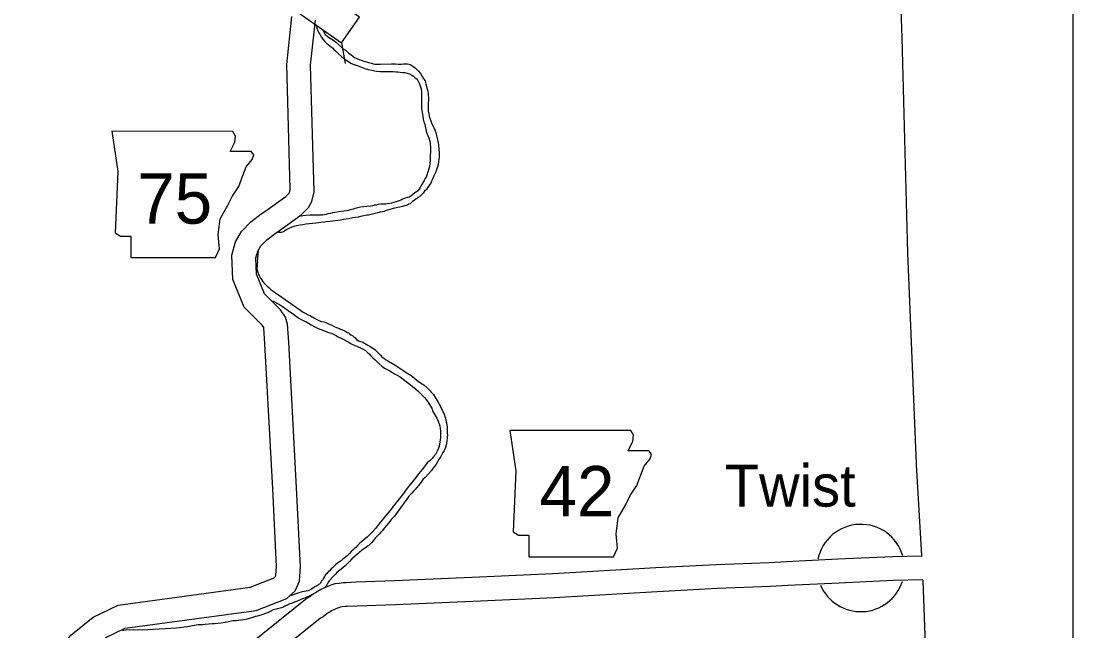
# Model space of a CAD drawing. Extents: x 1720274 to 1751788, y 372074 to 391887.
# Drawn here: x 1724650 to 1726742, y 388953 to 390167 of the extents above; entities that cross this region are included whole.
import ezdxf

# ---------------------------------------------------------------- set-up
doc = ezdxf.new("R2010")
doc.units = 0
for name, color, linetype in [('Level 10', 7, 'Continuous'), ('Level 2', 7, 'Continuous'), ('Level 20', 7, 'Continuous'), ('Level 21', 7, 'Continuous'), ('Level 24', 7, 'Continuous'), ('Level 9', 7, 'Continuous'), ('R_Draft', 7, 'Continuous')]:
    doc.layers.add(name, color=color, linetype=linetype)

msp = doc.modelspace()

# ---------------------------------------------------------------- linework, layer by layer
at = {"layer": 'Level 10'}
for points in [[(1724842.8, 389004.8), (1725105.5, 389040.3), (1725153, 389059), (1725155.6, 389061.3), (1725156.7, 389063.9), (1725158.1, 389081.6), (1725150.4, 389235.7), (1725134.8, 389524.6), (1725132.6, 389556), (1725132.4, 389556.9), (1725129, 389561.7), (1725093.8, 389597.5), (1725070.9, 389652.7), (1725069.1, 389701), (1725076.4, 389727.3), (1725088.4, 389747.9), (1725106.6, 389767.2), (1725127.6, 389783), (1725136.5, 389788.8), (1725176.1, 389817.5), (1725183.2, 389824.4), (1725183.4, 389824.9), (1725185.3, 389832.4), (1725178.1, 390080.5), (1725188.5, 390175.8)], [(1724856.7, 388958.8), (1725117.5, 388994.1), (1725178.5, 389018.1), (1725195.2, 389033.3), (1725203.3, 389052.4), (1725205.7, 389080.8), (1725197.7, 389238.1), (1725182.1, 389527.6), (1725179.6, 389563.9), (1725175.9, 389577.3), (1725165.5, 389592.1), (1725134, 389624.1), (1725118, 389663), (1725116.7, 389695.4), (1725120.4, 389708.7), (1725126.6, 389719.3), (1725138.4, 389731.7), (1725154.9, 389744.2), (1725163.5, 389749.8), (1725206.8, 389781.2), (1725221.6, 389795.7), (1725228, 389807.7), (1725232.9, 389827.1), (1725225.5, 390078.6), (1725235.3, 390168.4)], [(1726442.2, 389102.2), (1726382.7, 389100.8), (1726274.3, 389095.9), (1726172.4, 389090.9), (1726137.4, 389089), (1726032.3, 389085), (1725912.1, 389078.5), (1725707.6, 389066.7), (1725561.2, 389060.1), (1725392.5, 389052.7), (1725316.3, 389050), (1725296.5, 389049.1), (1725290.4, 389048.8), (1725282.7, 389047.9), (1725273.8, 389046.7), (1725267.6, 389044.8), (1725261.2, 389042.3), (1725246, 389035.6), (1725239.4, 389031.8), (1725236.5, 389029.8), (1725231.6, 389026.9), (1725224.4, 389021.4), (1725218.7, 389018.3)], [(1726443.2, 389054.8), (1726384.3, 389053.4), (1726276.5, 389048.5), (1726174.9, 389043.5), (1726139.6, 389041.6), (1726034.5, 389037.6), (1725914.7, 389031.2), (1725710.1, 389019.4), (1725563.3, 389012.7), (1725394.4, 389005.4), (1725318.2, 389002.6), (1725298.6, 389001.8), (1725294.2, 389001.6), (1725288.7, 389000.9), (1725284.1, 389000.3), (1725283.1, 389000), (1725279.3, 388998.5), (1725267.5, 388993.3), (1725264.5, 388991.6), (1725261.9, 388989.8), (1725258.2, 388987.6), (1725250.3, 388981.6), (1725245.1, 388978.7)], [(1725218.7, 389018.3), (1724974.9, 388822.1)], [(1724661.1, 388686.1), (1724664.3, 388796.5), (1724695.8, 388863.1), (1724724.8, 388912.7), (1724748.7, 388944.8), (1724793.2, 388980.5), (1724842.8, 389004.8)], [(1725245.1, 388978.7), (1725004.5, 388785.1)], [(1724708.8, 388694.5), (1724711.4, 388785.3), (1724737.8, 388841), (1724764.3, 388886.5), (1724783.1, 388911.6), (1724818.7, 388940.3), (1724856.7, 388958.8)]]:
    msp.add_lwpolyline(points, dxfattribs=at)
at = {"layer": 'Level 2'}
for points in [[(1726441.2, 389103.1), (1726430.6, 389283.7), (1726430.4, 389285.5), (1726413.3, 389705), (1726402, 390133.2), (1726387.2, 390548.1), (1726369.4, 390969.9), (1725968.9, 390955)], [(1726443.9, 389052.9), (1726443.8, 389053.9)], [(1726517.5, 386794.1), (1726507.7, 387180.9), (1726508, 387187.3), (1726491.7, 387614.2), (1726479.2, 388029.9), (1726479.1, 388035), (1726467.4, 388445.5), (1726450.4, 388867), (1726450.4, 388871.1), (1726443.9, 389052.9)]]:
    msp.add_lwpolyline(points, dxfattribs=at)
at = {"layer": 'Level 20'}
msp.add_line((1725287.1, 390123.3), (1725294.1, 390082.2), dxfattribs=at)
msp.add_lwpolyline([(1725133.7, 390231.6), (1725287.1, 390123.3), (1725323.1, 390174.4), (1725169.8, 390282.7)], close=True, dxfattribs=at)
at = {"layer": 'Level 21'}
for points in [[(1724830.4, 389947.3), (1724842.4, 389867.1), (1724837.1, 389745.4), (1724847.8, 389738.8), (1724867.8, 389738.8), (1724867.8, 389696), (1725036.2, 389696), (1725044.2, 389713.4), (1725041.6, 389741.4), (1725045.6, 389773.5), (1725060.3, 389798.9), (1725069.6, 389817.6), (1725083, 389837.7), (1725091, 389859.1), (1725097.7, 389876.4), (1725109.7, 389891.1), (1725112.4, 389900.5), (1725107.1, 389907.2), (1725065.6, 389907.2), (1725075, 389925.9), (1725076.3, 389937.9), (1725070.8, 389947.1)], [(1725621.8, 389352), (1725633.9, 389271.8), (1725628.5, 389150.2), (1725639.2, 389143.5), (1725659.3, 389143.5), (1725659.3, 389100.7), (1725827.7, 389100.7), (1725835.7, 389118.1), (1725833, 389146.2), (1725837, 389178.3), (1725851.7, 389203.7), (1725861.1, 389222.4), (1725874.4, 389242.4), (1725882.5, 389263.8), (1725889.1, 389281.2), (1725901.2, 389295.9), (1725903.8, 389305.2), (1725898.5, 389311.9), (1725857.1, 389311.9), (1725866.4, 389330.6), (1725867.8, 389342.6), (1725862.2, 389351.9)]]:
    msp.add_lwpolyline(points, close=True, dxfattribs=at)
at = {"layer": 'Level 24'}
for start, end in [(16.0112, 168.3106), (202.9489, 342.1811)]:
    msp.add_arc((1726319.8, 389078.5), 86.9, start, end, dxfattribs=at)
at = {"layer": 'Level 9'}
for points in [[(1725236.8, 390159), (1725237.1, 390155.9), (1725238, 390152.3), (1725239.8, 390147.3), (1725242.2, 390143.2), (1725244, 390140.3), (1725246, 390136.3), (1725250.1, 390130.6), (1725253.5, 390126.9), (1725257, 390123), (1725267.5, 390114.9), (1725269.4, 390113.1), (1725272, 390110.3), (1725276.3, 390106), (1725281, 390101.5), (1725287, 390096), (1725291, 390093.1), (1725295.8, 390089.4), (1725300.7, 390086.1)], [(1725250.1, 390150.1), (1725250.9, 390147.2), (1725252.8, 390143.2), (1725254.8, 390140.2), (1725257.3, 390137.8), (1725259.3, 390135.7), (1725262.3, 390133.7), (1725265.3, 390132.2), (1725267.3, 390131.2), (1725270.1, 390129.1), (1725272.3, 390127.5), (1725277.3, 390123.7), (1725281.8, 390119.1), (1725290.1, 390111.5), (1725295, 390108.7), (1725301.3, 390103.4), (1725306, 390099.5), (1725313, 390094.1), (1725322.3, 390090.5), (1725326.4, 390089.1), (1725333.7, 390086.3), (1725337.1, 390085.3), (1725340.8, 390084.4), (1725343.4, 390083.8), (1725346.5, 390082.8), (1725347.6, 390082.6), (1725350, 390081.8), (1725353.1, 390081.2), (1725357.2, 390080.6), (1725361.3, 390080.7), (1725364, 390080.8), (1725386.6, 390081.5), (1725394.7, 390081.4), (1725400.7, 390081.2), (1725405.4, 390081.1), (1725409.7, 390081.4), (1725414.1, 390081.8), (1725418.2, 390081.8), (1725420.8, 390081.1), (1725423.9, 390080.3), (1725427.2, 390078.3), (1725429.5, 390076.4), (1725430.7, 390075.7), (1725434.4, 390072.9), (1725436.8, 390070.1), (1725439.7, 390067.5), (1725444.3, 390062.2), (1725447.3, 390056.4), (1725449.7, 390053.3), (1725451.6, 390050.1), (1725453.3, 390048), (1725454, 390045.3), (1725454.6, 390040.8), (1725457, 390034.1), (1725458.1, 390029.6), (1725458.5, 390026.6), (1725459.3, 390022.7), (1725459.7, 390018.9), (1725459.9, 390013.8), (1725460.1, 390008.8), (1725459.6, 390003.3), (1725459.7, 389998.3), (1725459.6, 389994.4), (1725459.2, 389990.9), (1725459.6, 389987.6), (1725460.6, 389983.5), (1725461.6, 389976.8), (1725464.7, 389968), (1725466.3, 389964.3), (1725472.7, 389950.1), (1725474.5, 389945), (1725475.5, 389941.9), (1725476.7, 389936.3), (1725478, 389930.2), (1725479, 389924.2), (1725479.9, 389920.5), (1725480.2, 389917.2), (1725480.6, 389913.7), (1725480.6, 389909.7), (1725481, 389906.6), (1725481, 389902.3), (1725481, 389897.4), (1725480.8, 389892), (1725480.2, 389886.5), (1725479.2, 389881), (1725478.1, 389876.7), (1725476.7, 389872.6), (1725474.7, 389866.9)], [(1725300.7, 390086.1), (1725305.6, 390082.9), (1725310.5, 390081.1), (1725314.4, 390079.6), (1725320, 390077.5), (1725326.6, 390075.1), (1725333.5, 390072.5), (1725339.8, 390070.5), (1725347.5, 390069), (1725357, 390066.7), (1725363.8, 390066), (1725368.1, 390066.1), (1725373.5, 390066.2), (1725378.8, 390066.4), (1725389.9, 390066.2), (1725395, 390065.9), (1725399, 390065.4), (1725403.8, 390065), (1725409.1, 390064.2), (1725412.9, 390064.2), (1725417.4, 390063.3), (1725422.1, 390061.5), (1725426.7, 390059.2), (1725430, 390056.9), (1725433.2, 390054.3), (1725437.4, 390051.1), (1725439, 390048.2), (1725440.5, 390045.8), (1725441.8, 390043), (1725443, 390040.1), (1725444.2, 390035.7), (1725445.5, 390032), (1725446.1, 390025.7)], [(1725446.1, 390025.7), (1725446.2, 390015), (1725445.9, 390002.9), (1725446.1, 389999.5), (1725446.3, 389994.6), (1725446.3, 389992), (1725446.5, 389989.7), (1725447.8, 389985.6), (1725448.3, 389981.2), (1725448.5, 389977.4), (1725449.4, 389971.6), (1725450.6, 389966.4), (1725452.8, 389960.6), (1725455.2, 389947.4), (1725457.5, 389941.9), (1725459, 389938.8), (1725460.7, 389934.3), (1725462.3, 389929.5), (1725463.5, 389924.8), (1725463.8, 389911.7), (1725464.1, 389907.4), (1725464.1, 389905.3), (1725463.7, 389900.2), (1725463.6, 389894.7), (1725463.4, 389889.7), (1725462.9, 389884), (1725461.9, 389877.5), (1725459.4, 389868.1), (1725458.3, 389864.4), (1725457.4, 389861.8), (1725455.3, 389856.2), (1725453.6, 389853.1), (1725451.2, 389849.3), (1725449.4, 389846), (1725446.1, 389840.6), (1725443.3, 389835.5), (1725441.4, 389832.2), (1725438.8, 389829), (1725436.5, 389827.1), (1725433.2, 389824.6), (1725428.6, 389821.4), (1725424.8, 389818.4), (1725421.9, 389816.6), (1725418.4, 389815.9), (1725413.7, 389814.4), (1725408.7, 389812.1), (1725404.8, 389810.4), (1725401.9, 389809.1), (1725397.9, 389807.8), (1725391.4, 389805.9), (1725386.8, 389804.6), (1725382.3, 389803.5), (1725377.9, 389802.7), (1725375, 389802.5), (1725369.7, 389802.2), (1725365.1, 389802.2), (1725359.9, 389801.7), (1725355.9, 389800.7), (1725352.1, 389800.2), (1725348.7, 389799.3), (1725344.5, 389798.5), (1725337.4, 389797.8), (1725330.8, 389797.3), (1725324.6, 389796.4), (1725317.1, 389794.5), (1725313.8, 389793.7), (1725310.1, 389792.6), (1725304.5, 389790.9), (1725301.3, 389790), (1725297.1, 389789.4), (1725291.4, 389788.4), (1725286, 389787.8), (1725282, 389787.3), (1725274.4, 389786), (1725269.4, 389784.8), (1725264.6, 389783.8), (1725260.2, 389782.9), (1725256.8, 389781.8), (1725252.9, 389781.1), (1725249.5, 389780.3), (1725229.8, 389780.8), (1725224.3, 389780.7), (1725215.8, 389779.7), (1725210.2, 389779.2), (1725207.5, 389778.8), (1725204.4, 389778.7)], [(1725474.7, 389866.9), (1725473.4, 389863.9), (1725471.3, 389859.8), (1725470.1, 389856.7), (1725468.2, 389852.3), (1725466.3, 389848), (1725464.4, 389844), (1725462.3, 389840.6), (1725459.4, 389836.7), (1725455.8, 389831.5), (1725452.1, 389827.9), (1725449.2, 389824.3), (1725446.9, 389821.3), (1725443.2, 389818.3), (1725439.1, 389815.3), (1725436.1, 389813.2), (1725432.9, 389811.2), (1725431.3, 389809.8), (1725428.5, 389807.4), (1725423.4, 389803.1), (1725421, 389802.1), (1725418.7, 389801.1), (1725415.9, 389800), (1725412.2, 389799), (1725408.1, 389797.8), (1725403, 389796.5), (1725399.3, 389795.7), (1725395.9, 389795), (1725392.3, 389794.1), (1725387.9, 389793.4), (1725383.3, 389791.8), (1725378.5, 389790.4), (1725375.7, 389789.7), (1725374.9, 389789.3), (1725371.2, 389788.1), (1725368.3, 389787.4), (1725364.2, 389786.3), (1725361.7, 389785.5), (1725340.9, 389780.7), (1725337.3, 389780.6), (1725331.3, 389779.4), (1725327.2, 389778.3), (1725320.2, 389776.7), (1725309.8, 389774.9), (1725300.9, 389773.5), (1725290.8, 389771.6), (1725285.2, 389770.6), (1725264.2, 389768.1), (1725256.5, 389767), (1725253.2, 389766.8), (1725245.7, 389765.6), (1725241.1, 389765.1), (1725235.9, 389764.7), (1725229.3, 389764.2), (1725223, 389763.4), (1725216, 389762.3), (1725210.1, 389761.4), (1725204.9, 389760.3), (1725197.7, 389759.2), (1725192.4, 389757.8), (1725188.1, 389756.9), (1725182.5, 389753.9), (1725177, 389751.1), (1725173.8, 389748.8), (1725171.8, 389747.6), (1725166.9, 389746.1), (1725162.6, 389746.2), (1725162.6, 389746.4), (1725163, 389747.9), (1725163.1, 389748.2), (1725163.2, 389748.5), (1725164, 389749.1), (1725164.4, 389749.4)], [(1725121.5, 389708.6), (1725120.8, 389704.5), (1725120.4, 389701.3), (1725119.7, 389697), (1725119.8, 389694.3), (1725119.6, 389689.9), (1725119.8, 389687.2), (1725119.6, 389683), (1725119.5, 389680.2), (1725118.9, 389674.2), (1725119.3, 389670.6), (1725121.1, 389665.3), (1725122.1, 389662.6), (1725123, 389660.6), (1725124.5, 389658), (1725126.3, 389655.1), (1725127.9, 389652.7), (1725129.9, 389649.3), (1725132, 389646.8), (1725132.2, 389646.5), (1725133.9, 389644.2), (1725135.9, 389642.5), (1725137.8, 389640.7), (1725139, 389639.5), (1725140.5, 389638), (1725142.5, 389636.4), (1725145.3, 389633.8), (1725147.3, 389632.2), (1725151.2, 389629.1), (1725154, 389627.3), (1725161.8, 389622), (1725206.5, 389590.5), (1725211, 389587.8), (1725214.6, 389585.7), (1725220.9, 389582.4), (1725225.1, 389580.4), (1725233.4, 389575.8), (1725237.7, 389572.8), (1725242.3, 389570.6), (1725247.2, 389569.2), (1725252.5, 389568), (1725255.6, 389566.8), (1725261, 389564.5), (1725266.2, 389562.2), (1725271.1, 389559.5), (1725276.8, 389557.3), (1725280.9, 389555.7), (1725284.8, 389553.9), (1725289.1, 389552.6), (1725293.5, 389550.4), (1725295.6, 389549.1), (1725298.6, 389547.3), (1725300.8, 389546.2), (1725303.2, 389544.6), (1725305.6, 389542.6), (1725307.1, 389541.4), (1725309.3, 389540.1), (1725311.8, 389538.4), (1725313.3, 389537.4), (1725317.6, 389532.6), (1725321.2, 389530.5), (1725325.1, 389529.2), (1725329.3, 389527.6), (1725333.1, 389525.7), (1725339.6, 389522), (1725344.4, 389519.2), (1725349.5, 389516), (1725354, 389512.3), (1725357.1, 389509.4), (1725360.7, 389505.7), (1725364.5, 389501.8), (1725367.4, 389498.9), (1725371.2, 389495.8), (1725374.7, 389493.5), (1725379, 389490.8), (1725387.2, 389485.7), (1725393.5, 389482), (1725400.9, 389477.4), (1725409.2, 389471.9), (1725417.9, 389466.4), (1725425.5, 389461.2), (1725432.1, 389456.1), (1725437, 389452.1), (1725442.1, 389448.3), (1725447.4, 389445.1), (1725450.6, 389442.9), (1725457.4, 389437.1), (1725459.6, 389434.8), (1725463.2, 389430.8), (1725464.9, 389428.7), (1725467.4, 389426), (1725469.1, 389424.3), (1725470.6, 389422.2), (1725472.9, 389419)], [(1725149.8, 389610.2), (1725163.5, 389602.9), (1725169.8, 389598.7), (1725176, 389594.8), (1725183.5, 389589.1), (1725189.2, 389585.2), (1725194.2, 389581.5), (1725198.4, 389578.3), (1725203.6, 389574.7), (1725211, 389570.7), (1725216, 389568.7), (1725221.5, 389565.6), (1725226.6, 389562.3), (1725233.7, 389558.2), (1725240.5, 389555.2), (1725246.5, 389552.8), (1725251, 389551.2), (1725255.6, 389549.3), (1725261.1, 389547.2), (1725266.2, 389545.5), (1725272.5, 389542.8), (1725277.1, 389540.6), (1725280.6, 389538.5), (1725287.8, 389534.9), (1725301.5, 389528.1), (1725306.4, 389524.8), (1725309.6, 389523.3), (1725313.5, 389521.2), (1725317.4, 389519.8), (1725320.5, 389518.7), (1725325.1, 389516.8), (1725330.3, 389514.2), (1725335, 389510.9), (1725339.1, 389507.1), (1725341.8, 389504.3), (1725345.4, 389500.7), (1725349.7, 389496.3), (1725354.2, 389492.5), (1725358, 389488.8), (1725361.1, 389485.5), (1725367, 389479.8), (1725372.5, 389476.4), (1725379, 389472.7), (1725383.2, 389470.6), (1725388.5, 389467.2), (1725392.4, 389464.8), (1725397.6, 389461.9), (1725402.4, 389459.5), (1725404.4, 389458.1), (1725420.7, 389445.5), (1725424.5, 389442.9), (1725428.4, 389439.8), (1725434.6, 389434.4), (1725439.3, 389430.3), (1725452.5, 389416.8), (1725457, 389411.5), (1725460.1, 389406.9), (1725463.8, 389400.7), (1725466.7, 389396.3), (1725468.9, 389390.1), (1725476.5, 389376.8), (1725479.3, 389370.7), (1725482.3, 389361.1), (1725483.8, 389350.9), (1725484, 389346.3)], [(1725472.9, 389419), (1725479.7, 389406.8), (1725481.6, 389404.2), (1725484, 389400), (1725485.3, 389396.7), (1725487.8, 389391.8), (1725489.3, 389387.8), (1725491, 389384.3), (1725492.9, 389379.5), (1725493.7, 389377.2), (1725494.7, 389372.8), (1725495.4, 389369.2), (1725495.6, 389367.1), (1725496.4, 389362.7), (1725497.1, 389359.6), (1725497.2, 389355.7), (1725497, 389353.7), (1725497.1, 389352.5), (1725497.1, 389348.7), (1725497.3, 389346.5), (1725497.6, 389343.5), (1725495.9, 389326.2), (1725495.2, 389323.1), (1725493.7, 389318.1), (1725491.1, 389312), (1725488.6, 389308), (1725486.6, 389304.2), (1725484.4, 389300.4), (1725480.3, 389293.4), (1725478.1, 389289.4), (1725475.1, 389284.9), (1725472.2, 389280.7), (1725470.6, 389278.9), (1725466, 389272.5), (1725460.9, 389266.7), (1725453.3, 389258.7), (1725449, 389254.7), (1725443.3, 389246.5), (1725440.2, 389242.6), (1725436.1, 389237.7), (1725432.8, 389234.3), (1725429.4, 389230.6), (1725427.4, 389228), (1725424.3, 389224.8), (1725421.3, 389221.7), (1725418.6, 389217.7), (1725398.9, 389191), (1725392.2, 389181.6), (1725386.8, 389175.9), (1725384.7, 389173.2), (1725381.3, 389168.2), (1725372.1, 389157.7), (1725368.3, 389153.3), (1725365.6, 389150.1), (1725362.1, 389146.1), (1725358.5, 389142.4), (1725354.1, 389137.9), (1725351.8, 389135.4), (1725349.9, 389132.7), (1725347.5, 389129.2), (1725346.3, 389128), (1725344.8, 389126.4), (1725343.2, 389125.1), (1725341.3, 389123.5), (1725339.9, 389122.3), (1725337.7, 389120.4), (1725334.8, 389118.4), (1725332.9, 389117.1), (1725331.7, 389116.4), (1725328.8, 389114.6), (1725327.1, 389113.2), (1725325.1, 389111.3), (1725322.5, 389109.2), (1725320, 389107.3), (1725316.1, 389104), (1725311.5, 389100.2), (1725307.8, 389096.7), (1725302.8, 389091.6), (1725297.5, 389086.1), (1725294.6, 389083), (1725289.5, 389078.8), (1725284, 389074), (1725280.7, 389071.7), (1725277.9, 389069.4), (1725275.5, 389067), (1725271.8, 389063.2), (1725269.5, 389060.7), (1725267.1, 389058.4), (1725266.4, 389057.4), (1725264.2, 389054.9), (1725262.8, 389053), (1725261.2, 389050.7), (1725258.7, 389046.4), (1725258, 389045), (1725255, 389040.8), (1725253.9, 389039.7)], [(1725484, 389346.3), (1725484, 389341.8), (1725484, 389337.2), (1725483.4, 389333.4), (1725482.4, 389328.8), (1725481.9, 389325.6), (1725481, 389320.6), (1725479.8, 389317), (1725478, 389312.3), (1725475.6, 389307.2), (1725474.1, 389304.4), (1725468.7, 389298.3), (1725467.1, 389296.6), (1725463.3, 389292.6), (1725458.4, 389288.1), (1725447.5, 389274.3), (1725440.9, 389266.2), (1725432, 389254.9), (1725421, 389241.4), (1725415.5, 389234.5), (1725410.1, 389226.7), (1725405.2, 389220.3), (1725398.8, 389212.6), (1725391.9, 389203.2), (1725383.2, 389192.3), (1725372.5, 389179.8), (1725366.3, 389172), (1725360.4, 389164.9), (1725354.4, 389157.2), (1725348.8, 389150.6), (1725342.4, 389143.9), (1725338.3, 389139.9), (1725332, 389135), (1725323.1, 389127.1), (1725319.4, 389123.8), (1725315.3, 389119.5), (1725312.9, 389117.1), (1725309.7, 389114.2), (1725306.4, 389111.2), (1725303.3, 389107.6), (1725301.1, 389105.6), (1725298.4, 389102.4), (1725295.8, 389100.6), (1725292.4, 389097.9), (1725289.1, 389095.2), (1725286.8, 389093.7), (1725278.8, 389088.2), (1725275.1, 389084.8), (1725272.5, 389081.9), (1725269.2, 389078.9), (1725266.4, 389076.5), (1725263, 389072.9), (1725261.1, 389071.3), (1725257.3, 389067.2), (1725256.1, 389065.9), (1725254.8, 389063.9), (1725253.3, 389061.4), (1725251, 389058.2), (1725250.4, 389057.2), (1725249.1, 389054.4), (1725247.6, 389052.2), (1725246.8, 389050.7), (1725245.3, 389049), (1725244.5, 389047.9), (1725243.2, 389046.5), (1725241.6, 389045.4), (1725239.7, 389044.2), (1725237.9, 389043.2), (1725236.5, 389042.2), (1725233.8, 389040.7), (1725227.6, 389036.3), (1725220.9, 389032.9), (1725208.7, 389030.8), (1725200, 389028.4), (1725186.8, 389023.7), (1725183.1, 389022.4)], [(1725227.1, 389025.1), (1725222.6, 389022.6), (1725215.7, 389019.2), (1725209.7, 389017.2), (1725204.8, 389015.1), (1725202, 389013.9), (1725195.7, 389011.4), (1725190.5, 389009.4), (1725187.6, 389008.1), (1725184.4, 389006.9), (1725181.9, 389005.9), (1725179.6, 389004.8), (1725175.9, 389003.2), (1725174.1, 389002.6), (1725172.4, 389001.5), (1725169.4, 388999.9), (1725167.8, 388999.4), (1725165.1, 388998.3), (1725149.2, 388994.4)], [(1724851.8, 388954.9), (1724853.5, 388955.1), (1724858.2, 388955.4), (1724873, 388955.9), (1724878.3, 388955.6), (1724884.2, 388955.8), (1724891.8, 388955.4), (1724901.6, 388956.1), (1724959.2, 388959.5), (1724964.4, 388960), (1724974.3, 388961.3), (1724980.5, 388962), (1724990.7, 388963.9), (1725002, 388965.8), (1725010.9, 388966.3), (1725015.5, 388966.6), (1725030, 388968.2), (1725034.7, 388968.3), (1725047, 388969.7), (1725055.8, 388970.8), (1725071, 388973.8), (1725077.4, 388974.3), (1725087, 388975.1), (1725092.4, 388976.1), (1725099.7, 388977.4), (1725111.3, 388980.8), (1725116.3, 388982.5), (1725120.5, 388983.5), (1725131.1, 388986.8), (1725138.9, 388989.3), (1725143.4, 388991.5), (1725144.8, 388992.2), (1725146.9, 388993.2), (1725148.3, 388993.9), (1725149.2, 388994.4)]]:
    msp.add_lwpolyline(points, dxfattribs=at)
at = {"layer": 'R_Draft'}
msp.add_lwpolyline([(1720610.3, 391249.6), (1726741.8, 391249.6), (1726741.8, 384893.1), (1720610.3, 384893.1)], close=True, dxfattribs=at)

# ---------------------------------------------------------------- texts
at = {"layer": 'Level 21'}
for s, p in [('75', (1724880.8, 389763.6)), ('42', (1725681, 389181.3))]:
    msp.add_text(s, height=100.11, dxfattribs=at).set_placement(p)
at = {"layer": 'Level 24'}
msp.add_text('Twist', height=83.42, dxfattribs=at).set_placement((1726049.4, 389200.6))

doc.saveas('drawing.dxf')
